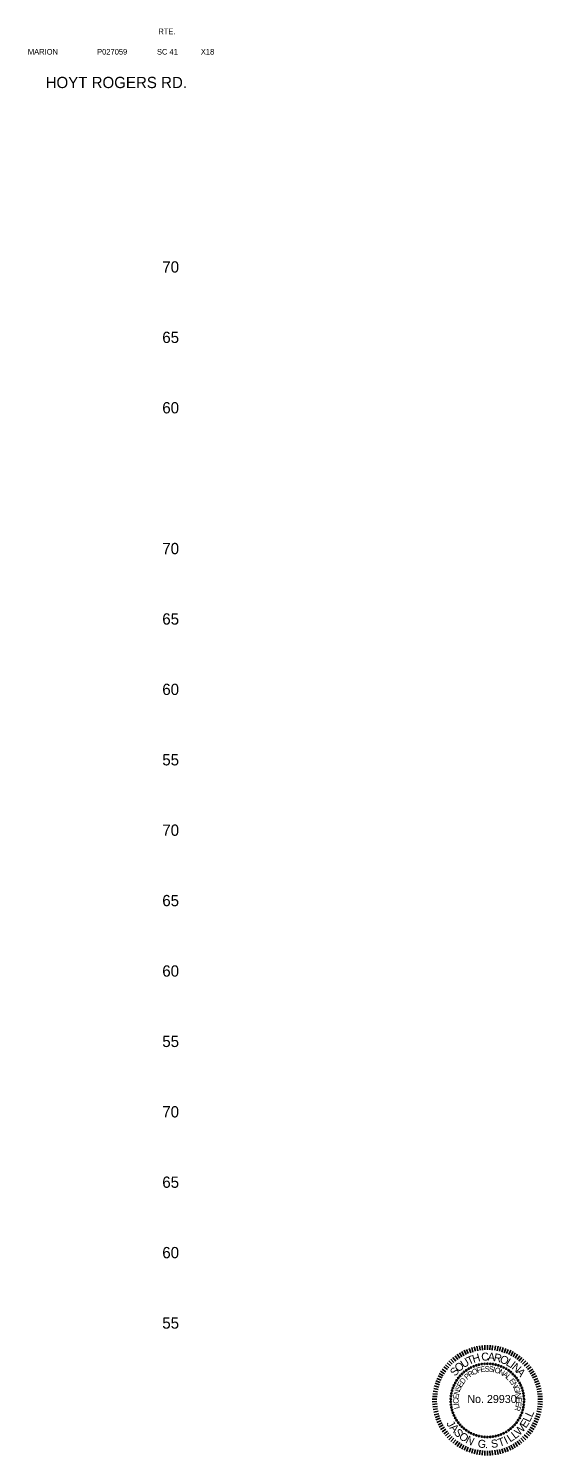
# Model space of a CAD drawing. Extents: x 1001 to 1184, y 1001 to 1217.
# Drawn here: x 1147.4 to 1183.9, y 1001 to 1102.3 of the extents above; entities that cross this region are included whole.
import ezdxf

# ---------------------------------------------------------------- set-up
doc = ezdxf.new("R2010")
doc.units = 0
for name, color, linetype in [('RD_HC_Cl', 7, 'Continuous'), ('RD_SHT_TX', 7, 'Continuous'), ('RD_TX_PEShield', 7, 'Continuous'), ('RD_XS_TX_Elev_EX', 7, 'Continuous')]:
    doc.layers.add(name, color=color, linetype=linetype)

# ---------------------------------------------------------------- blocks, each defined once
blk = doc.blocks.new('STILLWELL')
at = {"layer": 'RD_TX_PEShield'}
for p, q in [((-21.1, 28.1), (-23, 30.7)), ((-19.7, 29.1), (-21.5, 31.8)), ((-18.2, 30), (-19.9, 32.8)), ((-16.7, 30.8), (-18.2, 33.7)), ((-15.1, 31.6), (-16.5, 34.6)), ((-13.6, 32.3), (-14.8, 35.3)), ((-11.9, 32.9), (-13, 36)), ((-10.3, 33.4), (-11.2, 36.6)), ((-8.6, 33.9), (-9.4, 37.1)), ((-6.9, 34.3), (-7.5, 37.5)), ((-5.2, 34.6), (-5.7, 37.8)), ((-3.5, 34.8), (-3.8, 38)), ((-1.8, 34.9), (-1.9, 38.2)), ((0, 34.9), (0, 38.2)), ((1.7, 34.9), (1.9, 38.2)), ((3.4, 34.8), (3.7, 38)), ((5.2, 34.6), (5.6, 37.8)), ((6.9, 34.3), (7.5, 37.5)), ((8.6, 33.9), (9.3, 37.1)), ((10.2, 33.4), (11.2, 36.6)), ((11.9, 32.9), (13, 36)), ((13.5, 32.3), (14.7, 35.3)), ((15.1, 31.6), (16.5, 34.6)), ((16.6, 30.8), (18.2, 33.7)), ((18.2, 30), (19.8, 32.8)), ((19.6, 29.1), (21.4, 31.8)), ((21.1, 28.1), (23, 30.7)), ((-29.5, 19.4), (-32.2, 21.3)), ((-28.5, 20.9), (-31.1, 22.8)), ((-27.4, 22.2), (-29.9, 24.3)), ((-26.3, 23.5), (-28.7, 25.7)), ((-25.1, 24.7), (-27.4, 27.1)), ((-23.8, 25.9), (-26, 28.4)), ((-22.5, 27), (-24.5, 29.6)), ((22.4, 27), (24.5, 29.6)), ((23.8, 25.9), (25.9, 28.4)), ((25, 24.7), (27.3, 27.1)), ((26.2, 23.5), (28.6, 25.7)), ((27.4, 22.2), (29.9, 24.3)), ((28.5, 20.9), (31.1, 22.8)), ((29.5, 19.4), (32.2, 21.3)), ((-34.1, 10.2), (-37.2, 11.2)), ((-33.6, 11.8), (-36.6, 12.9)), ((-32.9, 13.4), (-35.9, 14.7)), ((-32.2, 15), (-35.1, 16.4)), ((-31.4, 16.5), (-34.2, 18.1)), ((-30.5, 18), (-33.3, 19.7)), ((30.4, 18), (33.2, 19.7)), ((31.3, 16.5), (34.2, 18.1)), ((32.1, 15), (35.1, 16.4)), ((32.9, 13.4), (35.9, 14.7)), ((33.5, 11.8), (36.6, 12.9)), ((34.1, 10.2), (37.2, 11.2)), ((-35.9, -0.1), (-39.2, 0)), ((-35.8, 1.7), (-39.1, 1.9)), ((-35.6, 3.4), (-38.9, 3.8)), ((-35.4, 5.1), (-38.6, 5.7)), ((-35.1, 6.8), (-38.2, 7.5)), ((-34.6, 8.5), (-37.8, 9.4)), ((34.6, 8.5), (37.7, 9.4)), ((35, 6.8), (38.2, 7.5)), ((35.3, 5.1), (38.5, 5.7)), ((35.6, 3.4), (38.8, 3.8)), ((35.7, 1.7), (39, 1.9)), ((35.8, -0.1), (39.1, 0)), ((-35.9, -1.8), (-39.2, -1.9)), ((-35.8, -3.5), (-39.1, -3.8)), ((-35.6, -5.3), (-38.9, -5.6)), ((-35.4, -7), (-38.6, -7.5)), ((-35.1, -8.7), (-38.2, -9.4)), ((35, -8.7), (38.2, -9.4)), ((35.3, -7), (38.5, -7.5)), ((35.6, -5.3), (38.8, -5.6)), ((35.7, -3.5), (39, -3.8)), ((35.8, -1.8), (39.1, -1.9)), ((-34.6, -10.4), (-37.8, -11.2)), ((-34.1, -12), (-37.2, -13)), ((-33.6, -13.6), (-36.6, -14.8)), ((-32.9, -15.3), (-35.9, -16.6)), ((-32.2, -16.8), (-35.1, -18.3)), ((-31.4, -18.4), (-34.2, -19.9)), ((-30.5, -19.9), (-33.3, -21.6)), ((30.4, -19.9), (33.2, -21.6)), ((31.3, -18.4), (34.2, -19.9)), ((32.1, -16.8), (35.1, -18.3)), ((32.9, -15.3), (35.9, -16.6)), ((33.5, -13.6), (36.6, -14.8)), ((34.1, -12), (37.2, -13)), ((34.6, -10.4), (37.7, -11.2)), ((-29.5, -21.3), (-32.2, -23.2)), ((-28.5, -22.7), (-31.1, -24.7)), ((-27.4, -24.1), (-29.9, -26.2)), ((-26.3, -25.4), (-28.7, -27.6)), ((-25.1, -26.6), (-27.4, -28.9)), ((-23.8, -27.8), (-26, -30.2)), ((-22.5, -28.9), (-24.5, -31.4)), ((-21.1, -29.9), (-23, -32.6)), ((21.1, -29.9), (23, -32.6)), ((22.4, -28.9), (24.5, -31.4)), ((23.8, -27.8), (25.9, -30.2)), ((25, -26.6), (27.3, -28.9)), ((26.2, -25.4), (28.6, -27.6)), ((27.4, -24.1), (29.9, -26.2)), ((28.5, -22.7), (31.1, -24.7)), ((29.5, -21.3), (32.2, -23.2)), ((-19.7, -30.9), (-21.5, -33.7)), ((-18.2, -31.8), (-19.9, -34.7)), ((-16.7, -32.7), (-18.2, -35.6)), ((-15.1, -33.5), (-16.5, -36.4)), ((-13.6, -34.1), (-14.8, -37.2)), ((-11.9, -34.8), (-13, -37.8)), ((-10.3, -35.3), (-11.2, -38.4)), ((-8.6, -35.8), (-9.4, -38.9)), ((-6.9, -36.1), (-7.5, -39.3)), ((-5.2, -36.4), (-5.7, -39.7)), ((-3.5, -36.6), (-3.8, -39.9)), ((-1.8, -36.8), (-1.9, -40)), ((0, -36.8), (0, -40.1)), ((1.7, -36.8), (1.9, -40)), ((3.4, -36.6), (3.7, -39.9)), ((5.2, -36.4), (5.6, -39.7)), ((6.9, -36.1), (7.5, -39.3)), ((8.6, -35.8), (9.3, -38.9)), ((10.2, -35.3), (11.2, -38.4)), ((11.9, -34.8), (13, -37.8)), ((13.5, -34.1), (14.7, -37.2)), ((15.1, -33.5), (16.5, -36.4)), ((16.6, -32.7), (18.2, -35.6)), ((18.2, -31.8), (19.8, -34.7)), ((19.6, -30.9), (21.4, -33.7))]:
    blk.add_line(p, q, dxfattribs=at)
for centre in [(-15, 20.4), (-13.3, 21.5), (-11.6, 22.4), (-9.8, 23.2), (-7.9, 23.9), (-6, 24.4), (-4, 24.8), (-2, 25), (0, 25.1), (2, 25), (3.9, 24.8), (5.9, 24.4), (7.8, 23.9), (9.7, 23.2), (11.5, 22.4), (13.3, 21.5), (15, 20.4), (-23.8, 9.7), (-22.9, 11.5), (-21.9, 13.2), (-20.7, 14.9), (-19.5, 16.4), (-18.1, 17.8), (-16.6, 19.2), (16.5, 19.2), (18, 17.8), (19.4, 16.4), (20.7, 14.9), (21.8, 13.2), (22.9, 11.5), (23.7, 9.7), (-26.1, 0.1), (-25.9, 2.1), (-25.6, 4), (-25.1, 6), (-24.5, 7.9), (24.5, 7.9), (25.1, 6), (25.5, 4), (25.8, 2.1), (26, 0.1), (-26.1, -1.9), (-25.9, -3.9), (-25.6, -5.9), (-25.1, -7.8), (-24.5, -9.7), (24.5, -9.7), (25.1, -7.8), (25.5, -5.9), (25.8, -3.9), (26, -1.9), (-23.8, -11.6), (-22.9, -13.4), (-21.9, -15.1), (-20.7, -16.7), (-19.5, -18.3), (-18.1, -19.7), (18, -19.7), (19.4, -18.3), (20.7, -16.7), (21.8, -15.1), (22.9, -13.4), (23.7, -11.6), (-16.6, -21), (-15, -22.2), (-13.3, -23.3), (-11.6, -24.3), (-9.8, -25.1), (-7.9, -25.8), (-6, -26.3), (-4, -26.7), (-2, -26.9), (0, -27), (2, -26.9), (3.9, -26.7), (5.9, -26.3), (7.8, -25.8), (9.7, -25.1), (11.5, -24.3), (13.3, -23.3), (15, -22.2), (16.5, -21)]:
    blk.add_circle(centre, 0.49, dxfattribs=at)
for s, height, rotation, p in [('T', 5.68, 23.5044, (-13.2, 24.1)), ('H', 5.68, 16.1357, (-9.9, 25.6)), ('C', 5.68, 4.076, (-4.2, 27.1)), ('A', 5.68, 355.3651, (0.1, 27.4)), ('R', 5.68, 347.3188, (4.1, 27.1)), ('O', 5.68, 338.6079, (8.3, 26.2)), ('S', 5.68, 49.6435, (-22.9, 15.8)), ('O', 5.68, 41.5972, (-20.4, 18.8)), ('U', 5.68, 32.2152, (-16.9, 21.8)), ('O', 3.92, 24.9735, (-10, 16.9)), ('F', 3.92, 15.9995, (-7.1, 18.3)), ('E', 3.92, 8.9511, (-4.7, 19)), ('S', 3.92, 1.2546, (-1.9, 19.4)), ('S', 3.92, 353.558, (0.8, 19.5)), ('I', 3.92, 345.8615, (3.5, 19.2)), ('O', 3.92, 342.6583, (4.7, 19)), ('N', 3.92, 333.6842, (7.7, 18)), ('L', 5.68, 329.226, (12.6, 24.4)), ('I', 5.68, 322.5218, (15.5, 22.8)), ('N', 5.68, 319.1729, (16.8, 21.8)), ('A', 5.68, 310.4621, (20.1, 19)), ('E', 3.92, 60.2341, (-18.5, 7.9)), ('D', 3.92, 52.5376, (-17.1, 10.3)), ('P', 3.92, 41.0022, (-14.5, 13.5)), ('R', 3.92, 33.3057, (-12.5, 15.3)), ('A', 3.92, 325.3521, (10.4, 16.7)), ('L', 3.92, 317.6555, (12.6, 15.1)), ('E', 3.92, 308.0396, (15.1, 12.8)), ('N', 3.92, 300.343, (16.8, 10.6)), ('C', 3.92, 92.2915, (-20.4, -3.2)), ('E', 3.92, 83.9594, (-20.5, -0.2)), ('N', 3.92, 76.2628, (-20.2, 2.5)), ('S', 3.92, 67.9307, (-19.5, 5.4)), ('G', 3.92, 292.0109, (18.3, 8.1)), ('I', 3.92, 283.0368, (19.5, 5.1)), ('N', 3.92, 279.8336, (19.8, 4)), ('E', 3.92, 271.5014, (20.3, 1.1)), ('I', 3.92, 95.4947, (-20.2, -4.3)), ('L', 3.92, 101.9075, (-19.7, -6.6)), ('R', 3.92, 256.1083, (20.1, -4.4)), ('E', 3.92, 263.8049, (20.4, -1.7)), ('L', 5.68, 65.098, (31.6, -13.3)), ('J', 5.68, 299.033, (-29.4, -17.3)), ('A', 5.68, 310.5887, (-27.2, -20.6)), ('W', 5.68, 47.0518, (22.6, -26.4)), ('E', 5.68, 56.4327, (27.3, -21.1)), ('L', 5.68, 65.098, (30, -16.9)), ('S', 5.68, 310.5887, (-24.3, -24)), ('O', 5.68, 321.0072, (-20.8, -27.4)), ('N', 5.68, 333.4326, (-16, -30.8)), ('G', 5.68, 352.2045, (-7.2, -34.2)), ('S', 5.68, 8.0826, (2.9, -34.8)), ('T', 5.68, 18.9019, (8.5, -33.9)), ('I', 5.68, 25.3991, (13.3, -32.2)), ('L', 5.68, 34.0644, (16.2, -30.9)), ('L', 5.68, 37.6708, (19.6, -28.7)), ('.', 5.68, 0.8698, (-1.8, -34.9))]:
    blk.add_text(s, height=height, rotation=rotation, dxfattribs=at).set_placement(p)
blk.add_text('No. 29930', height=5.68, dxfattribs=at).set_placement((-14.3, -2.8))

msp = doc.modelspace()

# ---------------------------------------------------------------- block references
at = {"layer": 'RD_HC_Cl', "xscale": 0.1, "yscale": 0.10000000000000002}
msp.add_blockref('STILLWELL', (1180, 1005), dxfattribs=at)

# ---------------------------------------------------------------- texts
at = {"layer": 'RD_SHT_TX'}
for s, height, p in [('RTE.', 0.4, (1156.62, 1101.93)), ('MARION', 0.4, (1147.35, 1100.48)), ('P027059', 0.4, (1152.27, 1100.48)), ('SC 41', 0.4, (1156.52, 1100.48)), ('X18', 0.4, (1159.64, 1100.48)), ('HOYT ROGERS RD.', 0.8, (1148.61, 1098.1))]:
    msp.add_text(s, height=height, dxfattribs=at).set_placement(p)
at = {"layer": 'RD_XS_TX_Elev_EX'}
for s, p in [('70', (1156.9, 1085)), ('65', (1156.9, 1080)), ('60', (1156.9, 1075)), ('70', (1156.9, 1065)), ('65', (1156.9, 1060)), ('60', (1156.9, 1055)), ('55', (1156.9, 1050)), ('70', (1156.9, 1045)), ('65', (1156.9, 1040)), ('60', (1156.9, 1035)), ('55', (1156.9, 1030)), ('70', (1156.9, 1025)), ('65', (1156.9, 1020)), ('60', (1156.9, 1015)), ('55', (1156.9, 1010))]:
    msp.add_text(s, height=0.8, dxfattribs=at).set_placement(p)

doc.saveas('drawing.dxf')
